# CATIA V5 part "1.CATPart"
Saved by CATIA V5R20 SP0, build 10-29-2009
Part number: Part1
Bounding box of the stored display mesh (mm): x -64.77 to 64.468, y -25.4 to 177.8, z -38.1 to 51.88
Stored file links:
  E:\Ehsan\Amoozesh\CATIA\CATIA Course\Advanced\Videos\Session-13\1.CATPart
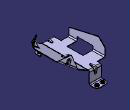
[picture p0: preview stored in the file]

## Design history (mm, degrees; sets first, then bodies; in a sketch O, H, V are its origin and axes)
SheetMetalParameters1: Thickness 1.27, BendRadius 3.175, KFactor 0.424743 {= log(min(100,max(20*SheetMetalParameters1.BendRadius,SheetMetalParameters1.Thickness)/SheetMetalParameters1.Thickness))/log(100)/2}, ReliefRadialLength 1, ReliefAxialLength 2, MinimumBendRadius 0
Set1
  Point1: type Center, Curve edge [face of d_NewWallOnEdge2 | face of Corner1]
  Point2: type Center, Curve edge [face of d_NewWallOnEdge2 | face of Corner1]
  Point3: type Center, Curve edge [face of d_NewWallOnEdge2 | face of Corner1]
  Point4: type Center, Curve edge [face of d_NewWallOnEdge2 | face of Corner1]
  Point5: type OnCurve, Support edge [face of d_NewWallOnEdge1 | face of Wall1], Ratio 0.5
  Point6: type OnCurve, Support edge [face of d_NewWallOnEdge1 | face of Wall1], Ratio 0.5
  Point7: type OnCurve, Support edge [face of FlatBend1 | face of d_NewWallOnEdge3], Ratio 0.5
  Point8: type OnCurve, Support edge [face of FlatBend1 | face of d_NewWallOnEdge3], Ratio 0.5
  Point9: type OnCurve, Support edge [face of d_NewWallOnEdge3 | face of d_NewWallOnEdge3], Ratio 0.5
Body1 (main body)
  Sketch1 on xy-plane, origin (0, 0, 0), H (1, 0, 0), V (0, 1, 0)
    line L1 (0, 0) -> (0, 152.4)
    line L2 (0, 152.4) -> (-38.1, 152.4)
    line L3 (-38.1, 152.4) -> (-38.1, 139.7)
    line L4 (-38.1, 139.7) -> (-63.5, 139.7)
    line L5 (-63.5, 139.7) -> (-63.5, 101.6)
    line L6 (-63.5, 101.6) -> (-31.75, 101.6)
    line L7 (-31.75, 101.6) -> (-31.75, 50.8)
    line L8 (-31.75, 50.8) -> (-63.5, 50.8)
    point P8 (-63.5, 50.8)
    line L9 (-63.5, 50.8) -> (-63.5, 25.4)
    line L10 (-63.5, 25.4) -> (-38.1, 25.4)
    line L11 (-38.1, 25.4) -> (-38.1, 0)
    point P11 (-38.1, 0)
    line L12 (-38.1, 0) -> (0, 0)
    length L1 = 152.4
    length L2 = 38.1
    length L3 = 12.7
    length L4 = 25.4
    length L5 = 38.1
    length L6 = 31.75
    length L7 = 50.8
    length L9 = 25.4
    length L10 = 25.4
    vertical: L1 V, L3 V, L5 V, L7 V, L9 V, L11 V
    horizontal: L2 H, L4 H, L6 H, L8 H, L10 H, L12 H
    coincidence: P8 L5, P11 H
  Wall1: Thickness 1.27, Profile Sketch1
  d_NewWallOnEdge1: NewWallOnEdge_Length 38.1, KFacteur 0.424743 {= log(min(100,max(20*d_NewWallOnEdge1.Radius,SheetMetalParameters1.Thickness)/SheetMetalParameters1.Thickness))/log(100)/2}, NewWallOnEdge_HeightLimitOffset 0, NewWallOnEdge_WidthOffset1 0, NewWallOnEdge_WidthOffset2 0, NewWallOnEdge_Angle 90, NewWallOnEdge_BendRadiusValue 3.175 {= SheetMetalParameters1.BendRadius}, NewWallOnEdge_BendTable SheetMetalParameters1, NewWallOnEdge_Edge (edge [face of Wall1 | face of Wall1]; edge [face of Wall1 | face of Wall1]), NewWallOnEdge_GapValue 0
  d_NewWallOnEdge2: NewWallOnEdge_Length 25.4, NewWallOnEdge_HeightLimitOffset 0, NewWallOnEdge_WidthOffset1 0, NewWallOnEdge_WidthOffset2 0, NewWallOnEdge_Angle 90, NewWallOnEdge_BendRadiusValue 3.175 {= SheetMetalParameters1.BendRadius}, NewWallOnEdge_BendTable SheetMetalParameters1, NewWallOnEdge_Edge (edge [face of d_NewWallOnEdge1 | face of d_NewWallOnEdge1]; edge [face of d_NewWallOnEdge1 | face of d_NewWallOnEdge1]), NewWallOnEdge_GapValue 0, KFacteur 0.424743 {= log(min(100,max(20*d_NewWallOnEdge2.Radius,SheetMetalParameters1.Thickness)/SheetMetalParameters1.Thickness))/log(100)/2}
  Corner1: CornerRadius 10.16, CornerChamferEdges (edge [face of d_NewWallOnEdge2 | face of d_NewWallOnEdge2]; edge [face of d_NewWallOnEdge2 | face of d_NewWallOnEdge2]; edge [face of d_NewWallOnEdge2 | face of d_NewWallOnEdge2]; edge [face of d_NewWallOnEdge2 | face of d_NewWallOnEdge2])
  Sketch2 on face of d_NewWallOnEdge2, origin (-10.16, 167.64, -36.83), H (1, 0, 0), V (0, -1, 0)
    point P1 (0, 0)
    reference projected point E1 (0, 0) from Point3
    coincidence: E1 P1
  d_Stamp1: KFacteur 0.424743 {= SheetMetalParameters1.KFactor}, NewRoot_AttribNormalisation "No Standard", Stamp_FilletRadius 1.27, Stamp_IntersectFilletRadius 2
  Sketch3 on face of d_NewWallOnEdge2, origin (-27.94, 167.64, -38.1), H (1, 0, 0), V (0, -1, 0)
    point P1 (0, 0)
    reference projected point E1 (0, 0) from Point4
    coincidence: E1 P1
  d_Stamp2: KFacteur 0.424743 {= SheetMetalParameters1.KFactor}, NewRoot_AttribNormalisation "No Standard", Stamp_FilletRadius 1.27, Stamp_IntersectFilletRadius 2
  Sketch4 on face of d_NewWallOnEdge2, origin (-27.94, -15.24, -38.1), H (1, 0, 0), V (0, -1, 0)
    point P1 (0, 0)
    reference projected point E1 (0, 0) from Point2
    coincidence: E1 P1
  d_Stamp3: KFacteur 0.424743 {= SheetMetalParameters1.KFactor}, NewRoot_AttribNormalisation "No Standard", Stamp_FilletRadius 1.27, Stamp_IntersectFilletRadius 2
  Sketch5 on face of d_NewWallOnEdge2, origin (-10.16, -15.24, -38.1), H (1, 0, 0), V (0, -1, 0)
    point P1 (0, 0)
    reference projected point E1 (0, 0) from Point1
    coincidence: E1 P1
  d_Stamp4: KFacteur 0.424743 {= SheetMetalParameters1.KFactor}, NewRoot_AttribNormalisation "No Standard", Stamp_FilletRadius 1.27, Stamp_IntersectFilletRadius 2
  Wall2: Thickness 1.27, Profile Sketch12
  d_Bend1: Bend_Thickness 1.27, Bend_BendTable SheetMetalParameters1, Bend_KFactor 0.424743 {= log(min(100,max(20*d_Bend1.Bend_KFactorRadius,SheetMetalParameters1.Thickness)/SheetMetalParameters1.Thickness))/log(100)/2}, Bend_KFactorRadius 3.175 {= d_Bend1.CylindricalBendSurf_Radius}, Bend_Deduction -3.0554 {= (d_Bend1.CylindricalBendSurf_Radius+SheetMetalParameters1.Thickness*d_Bend1.Bend_KFactor)*(PI-abs(d_Bend1.BendSurf_OpenAngle))-2*(d_Bend1.CylindricalBendSurf_Radius+SheetMetalParameters1.Thickness)*tan(min((PI-abs(d_Bend1.BendSurf_OpenAngle)),(PI/2))/2)}, Bend_FirstSupport Wall2, Bend_SecondSupport Wall1
  Chamfer1: ChamferAngle 45, ChamferLength1 25.4, ChamferLength2 0.635, ChamferPropagation 1, ChamferReverse false, ChamferType 1, CornerChamferEdges edge [face of Wall2 | face of Wall2]
  d_NewWallOnEdge3: NewWallOnEdge_Length 38.1, NewWallOnEdge_HeightLimitOffset 0, NewWallOnEdge_WidthOffset1 0, NewWallOnEdge_WidthOffset2 0, NewWallOnEdge_Angle 150, NewWallOnEdge_BendRadiusValue 3.175 {= SheetMetalParameters1.BendRadius}, NewWallOnEdge_BendTable SheetMetalParameters1, NewWallOnEdge_Edge edge [face of Wall1 | face of Wall1], NewWallOnEdge_GapValue 0, KFacteur 0.424743 {= log(min(100,max(20*d_NewWallOnEdge3.Radius,SheetMetalParameters1.Thickness)/SheetMetalParameters1.Thickness))/log(100)/2}
  FlatBend1: FlatBendAngle 90, FlatBendAngle 90, Axis Sketch11, FixedPoint vertex [face of d_NewWallOnEdge3 | face of d_NewWallOnEdge3 | face of d_NewWallOnEdge3 | face of d_NewWallOnEdge3], FlatBendKFactor 0.424743 {= log(min(100,max(20*FlatBend1.FlatBendRadius,SheetMetalParameters1.Thickness)/SheetMetalParameters1.Thickness))/log(100)/2}, FlatBendKFactor 0.424743 {= log(min(100,max(20*FlatBend1.FlatBendRadius,SheetMetalParameters1.Thickness)/SheetMetalParameters1.Thickness))/log(100)/2}, FlatBendRadius 3.175 {= SheetMetalParameters1.BendRadius}, FlatBendRadius 3.175 {= SheetMetalParameters1.BendRadius}
  Sketch6 on , origin (-19.4754, 149.225, 1.27), H (1, 0, 0), V (0, 1, 0)
    point P1 (0, 0)
    reference projected point E1 (0, 0) from Point5
    coincidence: E1 P1
  d_Stamp5: NewRoot_AttribNormalisation "No Standard", Stamp_FilletRadius 1.27, Stamp_IntersectFilletRadius 2
  Sketch7 on , origin (-19.4754, 3.175, 1.27), H (1, 0, 0), V (0, 1, 0)
    point P1 (0, 0)
    reference projected point E1 (0, 0) from Point6
    coincidence: E1 P1
  d_Stamp6: NewRoot_AttribNormalisation "No Standard", Stamp_FilletRadius 1.27, Stamp_IntersectFilletRadius 2
  Sketch8 on , origin (47.5852, 132.3447, 32.4095), H (0.7906, -0.5477, -0.2739), V (0, 0.4472, -0.8944)
    point P1 (0, 0)
    reference projected point E1 (0, 0) from Point7
    coincidence: E1 P1
  d_Stamp7: NewRoot_AttribNormalisation "No Standard", Stamp_FilletRadius 1.27, Stamp_IntersectFilletRadius 2
  Sketch9 on , origin (47.5852, 20.0553, 32.4095), H (0.7906, 0.5477, -0.2739), V (0, 0.4472, 0.8944)
    point P1 (0, 0)
    reference projected point E1 (0, 0) from Point8
    coincidence: E1 P1
  d_Stamp8: NewRoot_AttribNormalisation "No Standard", Stamp_FilletRadius 1.27, Stamp_IntersectFilletRadius 2
  Sketch10 on , origin (1.3718, 76.2, 0.5955), H (0.866, 0, 0.5), V (0, -1, 0)
    point P1 (0, 0)
    reference projected point E1 (0, 0) from Point9
    coincidence: E1 P1
  d_Stamp9: NewRoot_AttribNormalisation "No Standard", Stamp_FilletRadius 1.27, Stamp_IntersectFilletRadius 2
  Sketch11 on face of d_NewWallOnEdge3, origin (-0.5499, 0, 0.9525), H (0, -1, 0), V (0.866, 0, 0.5)
    line L1 (-151.8645, 35.7345) -> (-112.331, 75.268)
    line L2 (-45.2107, 80.4097) -> (5.6814, 29.5176)
    reference projected point E1 (-3.175, 74.295) from vertex [face of d_NewWallOnEdge3 | face of d_NewWallOnEdge3 | face of d_NewWallOnEdge3]
    reference projected point E2 (-149.225, 74.295) from vertex [face of d_NewWallOnEdge3 | face of d_NewWallOnEdge3 | face of d_NewWallOnEdge3]
    angle L1 H = 45
    angle L2 H = 45
    distance L2 E1 = 25.4
    distance L1 E2 = 25.4
  Sketch12 on face of Wall1, origin (-63.5, 0, 0), H (0, -1, 0), V (0, 0, 1)
    projected line E1 (-50.8, 0) -> (-25.4, 0) from edge [face of Wall1 | face of Wall1]
    projected line E2 (-139.7, 0) -> (-101.6, 0) from edge [face of Wall1 | face of Wall1]
    line L1 (-25.4, 0) -> (-25.4, 25.4)
    line L2 (-139.7, 0) -> (-139.7, 50.8)
    line L3 (-139.7, 50.8) -> (-25.4, 25.4)
    line L4 (-101.6, 0) -> (-101.6, 12.7)
    line L5 (-101.6, 12.7) -> (-50.8, 12.7)
    line L6 (-50.8, 12.7) -> (-50.8, 0)
    length L1 = 25.4
    length L2 = 50.8
    length L4 = 12.7
    vertical: L1 V, L2 V, L4 V, L6 V
    horizontal: L5 H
